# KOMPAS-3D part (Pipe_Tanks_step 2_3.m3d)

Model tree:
1. X Axis
2. Y Axis
3. Z Axis  (labels: T-Bend Dn 50; Pipe Dn 50)
     Òîëùèíà ñòåíêè 1 = 1

Referenced files in C:\Documents and Settings\kashirsky\Мои документы\Camtasia Studio\Pipelines3D\Tanks\: Tanks_step 2.a3d
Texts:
  Pipe Dn 50
  Steel ASTM A295
  Three Point Plane
  Plane at Angle
  Line and Point Plane
  Axis through Two Vertices
  Axis of Feature
  Axis of Conical Surface
  Axis through Edge
  Trim by Surface
  Trim by Sketch
  Feature with No History
  Intersection Axis of Two Planes
  Two Line Plane
  Line and Face Plane
  Bend by line
  Hole in sheet body
  Cut in sheet body
  Point in CM
  Linear Dimension from Line to Point
  Surface Finish Symbol
  Geometric Tolerance Symbol
  Leader #1
  Leader #2
  Leader #3
  Shape Deviations and Datum
  Node point number
  Mark of coordination axis
  Node point designation
  Mark/Reference designation with leader
  Mark/reference designation on line
  Mark/Reference designation without leader
  T-Bend Dn 50
  Plane of section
